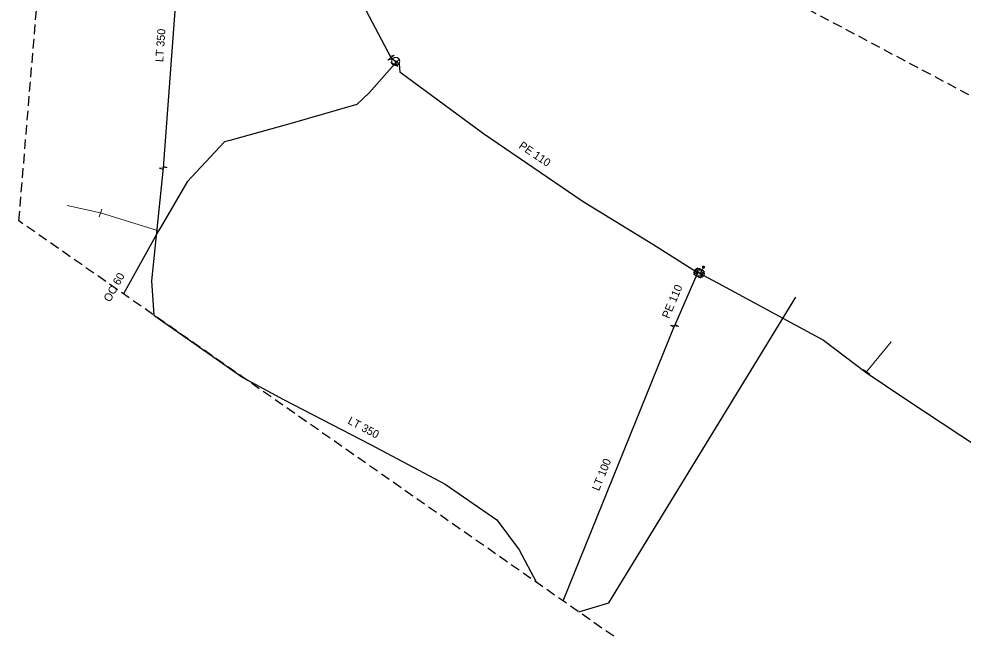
# Model space of a CAD drawing. Extents: x -692311 to -690519, y -971696 to -970899.
# Drawn here: x -692311.1 to -692193.2, y -971025.1 to -970948.8 of the extents above; entities that cross this region are included whole.
import ezdxf

# ---------------------------------------------------------------- set-up
doc = ezdxf.new("R2010")
doc.units = 0
doc.header["$LTSCALE"] = 0.4
doc.linetypes.add('MEDIUM_DASHED', pattern=[4.5, 3, -1.5])
for name, color, linetype, lineweight in [('1', 7, 'MEDIUM_DASHED', 25), ('13', 7, 'Continuous', 13), ('14', 7, 'Continuous', 13), ('17', 7, 'Continuous', 25), ('34', 7, 'Continuous', 13), ('47', 7, 'Continuous', 13), ('9', 7, 'Continuous', 13)]:
    doc.layers.add(name, color=color, linetype=linetype, lineweight=lineweight)

msp = doc.modelspace()

# ---------------------------------------------------------------- linework, layer by layer
at = {"layer": '1'}
msp.add_lwpolyline([(-691377.453, -971285.953), (-691463.283, -971177.096), (-691580.514, -971177.096), (-691632.849, -971177.096), (-691781.481, -971235.711), (-691971.982, -971202.217), (-692089.213, -971128.947), (-692311.114, -970974.035), (-692304.834, -970898.672), (-692166.669, -970971.942), (-691976.169, -971133.134), (-691904.993, -971149.882), (-691798.229, -971170.816), (-691674.718, -971116.387), (-691582.607, -971118.48), (-691415.135, -971114.294)], dxfattribs=at)
at = {"layer": '13'}
msp.add_line((-692205.219, -970992.88), (-692202.131, -970989.14), dxfattribs=at)
msp.add_lwpolyline([(-692293.654, -970975.29), (-692300.92, -970973.039), (-692305.065, -970972.14)], dxfattribs=at)
at = {"layer": '14'}
for p, q in [((-692264.039, -970954.129), (-692263.91, -970954.239)), ((-692225.989, -970980.612), (-692225.71, -970980.76)), ((-692205.28, -970992.96), (-692205.219, -970992.88))]:
    msp.add_line(p, q, dxfattribs=at)
for points in [[(-692226.256, -970980.478), (-692225.989, -970980.612), (-692225.851, -970980.364), (-692225.59, -970979.829)], [(-692226.57, -970980.329), (-692226.256, -970980.478), (-692226.41, -970980.75)]]:
    msp.add_lwpolyline(points, dxfattribs=at)
at = {"layer": '17'}
for p, q in [((-692290.69, -970935.236), (-692293.079, -970967.41)), ((-692226.41, -970980.75), (-692229.19, -970987.149)), ((-692243.126, -971021.498), (-692229.19, -970987.149))]:
    msp.add_line(p, q, dxfattribs=at)
for points in [[(-692264.611, -970953.671), (-692273.526, -970936.77), (-692274.836, -970914.581)], [(-692264.611, -970953.671), (-692264.039, -970954.129), (-692264.201, -970954.489)], [(-692264.201, -970954.489), (-692267.35, -970958.059), (-692268.91, -970959.52), (-692277.27, -970961.91), (-692284.76, -970964), (-692285.42, -970964.18), (-692290.07, -970969.149), (-692293.355, -970974.751), (-692293.654, -970975.29), (-692298.028, -970983.171)], [(-692263.91, -970954.239), (-692263.6, -970954.44), (-692263.539, -970955.42), (-692253.05, -970963.14), (-692240.6, -970971.62), (-692231.92, -970976.949), (-692226.57, -970980.329)], [(-692293.079, -970967.41), (-692294.55, -970981.53), (-692294.267, -970985.796), (-692283.119, -970993.579), (-692278.07, -970996.329), (-692267.17, -971001.96), (-692257.84, -971006.93), (-692251.399, -971011.379), (-692248.609, -971015.129), (-692246.436, -971019.188)], [(-692225.71, -970980.76), (-692223.739, -970981.829), (-692210.6, -970988.94), (-692205.28, -970992.96), (-692200.44, -970996.21), (-692188.77, -971003.92)], [(-692241.179, -971022.858), (-692237.418, -971021.743), (-692214.058, -970983.563)]]:
    msp.add_lwpolyline(points, dxfattribs=at)
at = {"layer": '34'}
for p, q in [((-692263.587, -970953.856), (-692264.233, -970954.62)), ((-692301.067, -970973.516), (-692300.771, -970972.561)), ((-692226.3, -970979.907), (-692226.84, -970980.749)), ((-692225.974, -970980.995), (-692226.844, -970980.503)), ((-692226.287, -970980.12), (-692225.414, -970980.608)), ((-692225.476, -970980.318), (-692225.944, -970981.201)), ((-692205.618, -970992.579), (-692204.82, -970993.181))]:
    msp.add_line(p, q, dxfattribs=at)
at = {"layer": '47'}
for p, q in [((-692265.007, -970953.99), (-692264.517, -970953.848)), ((-692263.761, -970954.746), (-692264.068, -970954.338)), ((-692292.571, -970967.364), (-692293.058, -970967.21)), ((-692229.69, -970987.051), (-692229.265, -970987.335))]:
    msp.add_line(p, q, dxfattribs=at)
for points in [[(-692265.007, -970953.99), (-692264.214, -970953.351), (-692264.704, -970953.493)], [(-692263.761, -970954.746), (-692264.64, -970954.231), (-692264.333, -970954.639)], [(-692292.571, -970967.364), (-692293.586, -970967.455), (-692293.099, -970967.609)], [(-692229.69, -970987.051), (-692228.689, -970987.246), (-692229.114, -970986.962)]]:
    msp.add_lwpolyline(points, dxfattribs=at)
for points in [[(-692263.648, -970954.441), (-692263.618, -970954.399), (-692263.592, -970954.353), (-692263.572, -970954.306), (-692263.555, -970954.256), (-692263.544, -970954.204), (-692263.539, -970954.152), (-692263.54, -970954.1), (-692263.546, -970954.048), (-692263.556, -970953.997), (-692263.573, -970953.947), (-692263.594, -970953.899), (-692263.621, -970953.854), (-692263.651, -970953.812), (-692263.687, -970953.773), (-692263.726, -970953.738), (-692263.768, -970953.708), (-692263.814, -970953.682), (-692263.862, -970953.661), (-692263.911, -970953.645), (-692263.963, -970953.634), (-692264.015, -970953.629), (-692264.068, -970953.629), (-692264.12, -970953.635), (-692264.17, -970953.646), (-692264.22, -970953.663), (-692264.268, -970953.684), (-692264.313, -970953.711), (-692264.355, -970953.741), (-692264.394, -970953.777), (-692264.429, -970953.816), (-692264.459, -970953.858), (-692264.485, -970953.904), (-692264.507, -970953.952), (-692264.522, -970954.001), (-692264.533, -970954.053), (-692264.538, -970954.104), (-692264.538, -970954.157), (-692264.533, -970954.209), (-692264.521, -970954.26), (-692264.504, -970954.31), (-692264.483, -970954.358), (-692264.457, -970954.403), (-692264.426, -970954.445), (-692264.39, -970954.484), (-692264.351, -970954.519), (-692264.309, -970954.549), (-692264.263, -970954.575), (-692264.216, -970954.596), (-692264.166, -970954.612), (-692264.114, -970954.623), (-692264.063, -970954.628), (-692264.011, -970954.628), (-692263.959, -970954.622), (-692263.907, -970954.611), (-692263.857, -970954.594), (-692263.809, -970954.573), (-692263.765, -970954.547), (-692263.722, -970954.516), (-692263.683, -970954.48)], [(-692263.975, -970954.18), (-692263.969, -970954.173), (-692263.965, -970954.165), (-692263.962, -970954.158), (-692263.959, -970954.15), (-692263.957, -970954.141), (-692263.957, -970954.132), (-692263.957, -970954.124), (-692263.957, -970954.115), (-692263.96, -970954.107), (-692263.962, -970954.099), (-692263.966, -970954.091), (-692263.97, -970954.083), (-692263.975, -970954.077), (-692263.98, -970954.07), (-692263.987, -970954.065), (-692263.994, -970954.059), (-692264.002, -970954.055), (-692264.009, -970954.052), (-692264.017, -970954.049), (-692264.026, -970954.047), (-692264.035, -970954.047), (-692264.043, -970954.047), (-692264.052, -970954.047), (-692264.061, -970954.049), (-692264.068, -970954.052), (-692264.076, -970954.056), (-692264.084, -970954.06), (-692264.09, -970954.065), (-692264.097, -970954.07), (-692264.102, -970954.077), (-692264.108, -970954.084), (-692264.112, -970954.092), (-692264.115, -970954.099), (-692264.118, -970954.107), (-692264.12, -970954.116), (-692264.121, -970954.124), (-692264.12, -970954.133), (-692264.12, -970954.142), (-692264.118, -970954.151), (-692264.115, -970954.158), (-692264.111, -970954.166), (-692264.107, -970954.174), (-692264.102, -970954.18), (-692264.097, -970954.187), (-692264.09, -970954.192), (-692264.083, -970954.198), (-692264.075, -970954.202), (-692264.068, -970954.205), (-692264.06, -970954.208), (-692264.051, -970954.21), (-692264.043, -970954.211), (-692264.034, -970954.21), (-692264.025, -970954.21), (-692264.017, -970954.207), (-692264.009, -970954.205), (-692264.001, -970954.201), (-692263.993, -970954.197), (-692263.987, -970954.192), (-692263.98, -970954.187)], [(-692225.803, -970980.691), (-692225.784, -970980.642), (-692225.769, -970980.592), (-692225.76, -970980.541), (-692225.756, -970980.489), (-692225.757, -970980.436), (-692225.765, -970980.384), (-692225.778, -970980.334), (-692225.795, -970980.284), (-692225.817, -970980.237), (-692225.845, -970980.192), (-692225.877, -970980.151), (-692225.914, -970980.113), (-692225.953, -970980.08), (-692225.997, -970980.05), (-692226.042, -970980.025), (-692226.091, -970980.006), (-692226.141, -970979.991), (-692226.193, -970979.982), (-692226.244, -970979.978), (-692226.297, -970979.979), (-692226.349, -970979.987), (-692226.4, -970979.999), (-692226.45, -970980.017), (-692226.497, -970980.039), (-692226.541, -970980.067), (-692226.582, -970980.099), (-692226.62, -970980.135), (-692226.653, -970980.175), (-692226.683, -970980.219), (-692226.708, -970980.264), (-692226.727, -970980.313), (-692226.742, -970980.363), (-692226.752, -970980.415), (-692226.755, -970980.466), (-692226.754, -970980.519), (-692226.747, -970980.571), (-692226.735, -970980.622), (-692226.717, -970980.671), (-692226.694, -970980.719), (-692226.666, -970980.763), (-692226.634, -970980.804), (-692226.599, -970980.842), (-692226.558, -970980.875), (-692226.514, -970980.905), (-692226.469, -970980.93), (-692226.42, -970980.949), (-692226.37, -970980.964), (-692226.319, -970980.974), (-692226.267, -970980.977), (-692226.214, -970980.976), (-692226.162, -970980.969), (-692226.112, -970980.956), (-692226.063, -970980.939), (-692226.015, -970980.916), (-692225.97, -970980.888), (-692225.929, -970980.856), (-692225.892, -970980.82), (-692225.858, -970980.78), (-692225.828, -970980.736)], [(-692225.542, -970980.836), (-692225.521, -970980.788), (-692225.505, -970980.738), (-692225.495, -970980.687), (-692225.489, -970980.635), (-692225.489, -970980.582), (-692225.496, -970980.53), (-692225.507, -970980.479), (-692225.524, -970980.43), (-692225.545, -970980.382), (-692225.571, -970980.337), (-692225.602, -970980.294), (-692225.638, -970980.256), (-692225.676, -970980.221), (-692225.719, -970980.191), (-692225.764, -970980.165), (-692225.812, -970980.144), (-692225.862, -970980.128), (-692225.914, -970980.117), (-692225.965, -970980.112), (-692226.018, -970980.112), (-692226.07, -970980.119), (-692226.121, -970980.13), (-692226.171, -970980.146), (-692226.219, -970980.167), (-692226.263, -970980.194), (-692226.306, -970980.225), (-692226.345, -970980.26), (-692226.379, -970980.299), (-692226.409, -970980.342), (-692226.435, -970980.387), (-692226.456, -970980.435), (-692226.472, -970980.485), (-692226.483, -970980.537), (-692226.488, -970980.588), (-692226.488, -970980.641), (-692226.482, -970980.693), (-692226.471, -970980.744), (-692226.455, -970980.794), (-692226.433, -970980.842), (-692226.406, -970980.886), (-692226.375, -970980.929), (-692226.341, -970980.967), (-692226.301, -970981.002), (-692226.258, -970981.032), (-692226.213, -970981.058), (-692226.165, -970981.079), (-692226.115, -970981.095), (-692226.064, -970981.106), (-692226.012, -970981.111), (-692225.959, -970981.111), (-692225.907, -970981.105), (-692225.857, -970981.094), (-692225.807, -970981.077), (-692225.759, -970981.055), (-692225.714, -970981.029), (-692225.671, -970980.998), (-692225.633, -970980.963), (-692225.598, -970980.924), (-692225.568, -970980.881)], [(-692226.181, -970980.512), (-692226.177, -970980.504), (-692226.176, -970980.496), (-692226.174, -970980.488), (-692226.174, -970980.48), (-692226.174, -970980.471), (-692226.175, -970980.462), (-692226.177, -970980.454), (-692226.18, -970980.446), (-692226.184, -970980.438), (-692226.188, -970980.431), (-692226.194, -970980.424), (-692226.2, -970980.418), (-692226.206, -970980.412), (-692226.212, -970980.407), (-692226.221, -970980.403), (-692226.229, -970980.399), (-692226.237, -970980.398), (-692226.245, -970980.396), (-692226.253, -970980.396), (-692226.262, -970980.396), (-692226.271, -970980.397), (-692226.279, -970980.399), (-692226.287, -970980.402), (-692226.296, -970980.406), (-692226.302, -970980.41), (-692226.309, -970980.416), (-692226.315, -970980.422), (-692226.321, -970980.428), (-692226.326, -970980.434), (-692226.33, -970980.443), (-692226.334, -970980.451), (-692226.335, -970980.459), (-692226.337, -970980.467), (-692226.337, -970980.475), (-692226.337, -970980.484), (-692226.337, -970980.492), (-692226.334, -970980.501), (-692226.331, -970980.509), (-692226.327, -970980.518), (-692226.323, -970980.524), (-692226.317, -970980.531), (-692226.311, -970980.537), (-692226.305, -970980.543), (-692226.299, -970980.548), (-692226.29, -970980.552), (-692226.282, -970980.556), (-692226.274, -970980.557), (-692226.266, -970980.559), (-692226.258, -970980.559), (-692226.249, -970980.559), (-692226.241, -970980.559), (-692226.232, -970980.556), (-692226.224, -970980.553), (-692226.216, -970980.549), (-692226.209, -970980.545), (-692226.202, -970980.539), (-692226.196, -970980.533), (-692226.19, -970980.527), (-692226.185, -970980.521)], [(-692225.915, -970980.648), (-692225.911, -970980.64), (-692225.909, -970980.632), (-692225.908, -970980.624), (-692225.907, -970980.616), (-692225.907, -970980.607), (-692225.908, -970980.598), (-692225.909, -970980.59), (-692225.912, -970980.582), (-692225.916, -970980.574), (-692225.92, -970980.566), (-692225.925, -970980.559), (-692225.931, -970980.553), (-692225.937, -970980.548), (-692225.944, -970980.542), (-692225.952, -970980.538), (-692225.96, -970980.534), (-692225.968, -970980.532), (-692225.976, -970980.531), (-692225.984, -970980.53), (-692225.993, -970980.53), (-692226.002, -970980.531), (-692226.01, -970980.532), (-692226.018, -970980.535), (-692226.027, -970980.539), (-692226.034, -970980.543), (-692226.041, -970980.548), (-692226.047, -970980.554), (-692226.052, -970980.56), (-692226.058, -970980.567), (-692226.062, -970980.575), (-692226.066, -970980.583), (-692226.068, -970980.591), (-692226.069, -970980.599), (-692226.07, -970980.607), (-692226.07, -970980.616), (-692226.07, -970980.624), (-692226.068, -970980.633), (-692226.065, -970980.641), (-692226.061, -970980.65), (-692226.057, -970980.657), (-692226.052, -970980.664), (-692226.046, -970980.67), (-692226.04, -970980.675), (-692226.033, -970980.681), (-692226.025, -970980.685), (-692226.017, -970980.689), (-692226.009, -970980.691), (-692226.001, -970980.692), (-692225.993, -970980.693), (-692225.984, -970980.693), (-692225.976, -970980.693), (-692225.967, -970980.691), (-692225.959, -970980.688), (-692225.951, -970980.684), (-692225.943, -970980.68), (-692225.936, -970980.675), (-692225.93, -970980.669), (-692225.925, -970980.663), (-692225.919, -970980.656)]]:
    msp.add_lwpolyline(points, close=True, dxfattribs=at)
at = {"layer": '9'}
for points in [[(-692225.716, -970979.829), (-692225.716, -970979.842), (-692225.713, -970979.855), (-692225.711, -970979.868), (-692225.706, -970979.88), (-692225.7, -970979.892), (-692225.693, -970979.903), (-692225.684, -970979.913), (-692225.674, -970979.923), (-692225.664, -970979.931), (-692225.654, -970979.938), (-692225.642, -970979.944), (-692225.63, -970979.949), (-692225.617, -970979.952), (-692225.603, -970979.954), (-692225.591, -970979.956), (-692225.578, -970979.955), (-692225.565, -970979.953), (-692225.552, -970979.95), (-692225.539, -970979.945), (-692225.527, -970979.939), (-692225.517, -970979.932), (-692225.507, -970979.924), (-692225.497, -970979.914), (-692225.489, -970979.904), (-692225.482, -970979.893), (-692225.476, -970979.881), (-692225.471, -970979.869), (-692225.468, -970979.856), (-692225.466, -970979.843), (-692225.463, -970979.83), (-692225.465, -970979.817), (-692225.467, -970979.804), (-692225.47, -970979.791), (-692225.475, -970979.779), (-692225.48, -970979.767), (-692225.488, -970979.756), (-692225.495, -970979.746), (-692225.505, -970979.736), (-692225.516, -970979.728), (-692225.527, -970979.721), (-692225.539, -970979.715), (-692225.551, -970979.71), (-692225.564, -970979.707), (-692225.576, -970979.705), (-692225.59, -970979.704), (-692225.603, -970979.704), (-692225.615, -970979.706), (-692225.629, -970979.709), (-692225.641, -970979.714), (-692225.652, -970979.72), (-692225.664, -970979.727), (-692225.674, -970979.735), (-692225.684, -970979.745), (-692225.691, -970979.755), (-692225.699, -970979.766), (-692225.705, -970979.778), (-692225.71, -970979.79), (-692225.713, -970979.803), (-692225.715, -970979.816)], [(-692225.696, -970979.829), (-692225.696, -970979.84), (-692225.695, -970979.851), (-692225.691, -970979.862), (-692225.688, -970979.872), (-692225.683, -970979.882), (-692225.677, -970979.891), (-692225.669, -970979.9), (-692225.662, -970979.908), (-692225.652, -970979.915), (-692225.644, -970979.921), (-692225.634, -970979.926), (-692225.624, -970979.93), (-692225.613, -970979.933), (-692225.602, -970979.936), (-692225.591, -970979.936), (-692225.58, -970979.936), (-692225.569, -970979.934), (-692225.558, -970979.931), (-692225.548, -970979.927), (-692225.538, -970979.922), (-692225.529, -970979.916), (-692225.52, -970979.909), (-692225.512, -970979.901), (-692225.505, -970979.892), (-692225.499, -970979.883), (-692225.494, -970979.873), (-692225.49, -970979.863), (-692225.487, -970979.852), (-692225.485, -970979.841), (-692225.483, -970979.83), (-692225.483, -970979.819), (-692225.485, -970979.808), (-692225.489, -970979.797), (-692225.493, -970979.787), (-692225.498, -970979.777), (-692225.504, -970979.768), (-692225.511, -970979.759), (-692225.519, -970979.751), (-692225.527, -970979.744), (-692225.537, -970979.738), (-692225.547, -970979.733), (-692225.556, -970979.729), (-692225.568, -970979.726), (-692225.578, -970979.724), (-692225.59, -970979.724), (-692225.601, -970979.723), (-692225.612, -970979.725), (-692225.623, -970979.728), (-692225.632, -970979.732), (-692225.642, -970979.737), (-692225.652, -970979.743), (-692225.661, -970979.75), (-692225.669, -970979.758), (-692225.676, -970979.767), (-692225.681, -970979.776), (-692225.686, -970979.786), (-692225.691, -970979.796), (-692225.694, -970979.807), (-692225.696, -970979.818)], [(-692225.677, -970979.829), (-692225.677, -970979.838), (-692225.676, -970979.847), (-692225.673, -970979.856), (-692225.669, -970979.864), (-692225.666, -970979.872), (-692225.661, -970979.88), (-692225.654, -970979.887), (-692225.649, -970979.893), (-692225.642, -970979.899), (-692225.634, -970979.904), (-692225.625, -970979.908), (-692225.618, -970979.911), (-692225.608, -970979.914), (-692225.6, -970979.915), (-692225.591, -970979.917), (-692225.581, -970979.916), (-692225.573, -970979.915), (-692225.564, -970979.912), (-692225.556, -970979.909), (-692225.548, -970979.905), (-692225.539, -970979.9), (-692225.532, -970979.894), (-692225.527, -970979.888), (-692225.521, -970979.881), (-692225.516, -970979.873), (-692225.512, -970979.865), (-692225.509, -970979.857), (-692225.505, -970979.848), (-692225.505, -970979.839), (-692225.502, -970979.83), (-692225.504, -970979.821), (-692225.505, -970979.812), (-692225.507, -970979.803), (-692225.511, -970979.795), (-692225.515, -970979.787), (-692225.52, -970979.779), (-692225.526, -970979.772), (-692225.532, -970979.766), (-692225.539, -970979.76), (-692225.547, -970979.755), (-692225.554, -970979.751), (-692225.563, -970979.748), (-692225.571, -970979.745), (-692225.581, -970979.744), (-692225.59, -970979.743), (-692225.598, -970979.743), (-692225.608, -970979.744), (-692225.617, -970979.747), (-692225.625, -970979.75), (-692225.632, -970979.754), (-692225.641, -970979.759), (-692225.647, -970979.765), (-692225.654, -970979.771), (-692225.659, -970979.778), (-692225.664, -970979.786), (-692225.669, -970979.794), (-692225.672, -970979.802), (-692225.674, -970979.811), (-692225.676, -970979.82)], [(-692225.657, -970979.829), (-692225.657, -970979.836), (-692225.656, -970979.843), (-692225.654, -970979.85), (-692225.652, -970979.856), (-692225.649, -970979.862), (-692225.645, -970979.868), (-692225.641, -970979.874), (-692225.636, -970979.879), (-692225.63, -970979.883), (-692225.624, -970979.887), (-692225.618, -970979.89), (-692225.612, -970979.893), (-692225.605, -970979.894), (-692225.598, -970979.897), (-692225.591, -970979.897), (-692225.583, -970979.897), (-692225.576, -970979.895), (-692225.57, -970979.894), (-692225.564, -970979.891), (-692225.556, -970979.888), (-692225.552, -970979.884), (-692225.546, -970979.88), (-692225.541, -970979.875), (-692225.537, -970979.869), (-692225.532, -970979.863), (-692225.529, -970979.857), (-692225.527, -970979.851), (-692225.525, -970979.844), (-692225.524, -970979.837), (-692225.522, -970979.83), (-692225.522, -970979.823), (-692225.524, -970979.816), (-692225.526, -970979.809), (-692225.529, -970979.803), (-692225.532, -970979.796), (-692225.536, -970979.791), (-692225.539, -970979.785), (-692225.544, -970979.78), (-692225.551, -970979.776), (-692225.556, -970979.772), (-692225.563, -970979.769), (-692225.569, -970979.766), (-692225.576, -970979.764), (-692225.583, -970979.763), (-692225.59, -970979.763), (-692225.597, -970979.763), (-692225.603, -970979.763), (-692225.61, -970979.765), (-692225.617, -970979.768), (-692225.623, -970979.771), (-692225.629, -970979.775), (-692225.635, -970979.779), (-692225.64, -970979.784), (-692225.644, -970979.79), (-692225.647, -970979.795), (-692225.651, -970979.802), (-692225.654, -970979.808), (-692225.654, -970979.815), (-692225.657, -970979.822)], [(-692225.637, -970979.829), (-692225.637, -970979.834), (-692225.637, -970979.839), (-692225.636, -970979.844), (-692225.634, -970979.848), (-692225.632, -970979.853), (-692225.629, -970979.857), (-692225.625, -970979.86), (-692225.622, -970979.864), (-692225.619, -970979.867), (-692225.615, -970979.87), (-692225.61, -970979.872), (-692225.605, -970979.874), (-692225.601, -970979.875), (-692225.596, -970979.877), (-692225.591, -970979.877), (-692225.586, -970979.877), (-692225.581, -970979.876), (-692225.576, -970979.875), (-692225.571, -970979.873), (-692225.566, -970979.871), (-692225.563, -970979.868), (-692225.559, -970979.865), (-692225.556, -970979.861), (-692225.553, -970979.858), (-692225.549, -970979.854), (-692225.548, -970979.849), (-692225.546, -970979.845), (-692225.544, -970979.84), (-692225.544, -970979.835), (-692225.543, -970979.83), (-692225.543, -970979.825), (-692225.544, -970979.82), (-692225.544, -970979.815), (-692225.547, -970979.811), (-692225.549, -970979.806), (-692225.552, -970979.802), (-692225.554, -970979.798), (-692225.558, -970979.795), (-692225.561, -970979.792), (-692225.566, -970979.789), (-692225.571, -970979.787), (-692225.575, -970979.785), (-692225.58, -970979.784), (-692225.585, -970979.783), (-692225.59, -970979.783), (-692225.595, -970979.783), (-692225.6, -970979.784), (-692225.605, -970979.784), (-692225.608, -970979.786), (-692225.614, -970979.788), (-692225.618, -970979.791), (-692225.62, -970979.794), (-692225.625, -970979.797), (-692225.627, -970979.801), (-692225.63, -970979.805), (-692225.632, -970979.81), (-692225.635, -970979.814), (-692225.636, -970979.819), (-692225.637, -970979.824)], [(-692225.617, -970979.829), (-692225.617, -970979.832), (-692225.618, -970979.835), (-692225.617, -970979.837), (-692225.615, -970979.84), (-692225.615, -970979.843), (-692225.613, -970979.845), (-692225.61, -970979.847), (-692225.608, -970979.849), (-692225.607, -970979.851), (-692225.605, -970979.853), (-692225.602, -970979.855), (-692225.598, -970979.856), (-692225.597, -970979.856), (-692225.593, -970979.857), (-692225.591, -970979.857), (-692225.588, -970979.857), (-692225.585, -970979.857), (-692225.581, -970979.856), (-692225.58, -970979.855), (-692225.576, -970979.854), (-692225.575, -970979.852), (-692225.571, -970979.85), (-692225.57, -970979.848), (-692225.569, -970979.846), (-692225.566, -970979.844), (-692225.566, -970979.841), (-692225.564, -970979.838), (-692225.564, -970979.836), (-692225.563, -970979.833), (-692225.561, -970979.83), (-692225.563, -970979.827), (-692225.563, -970979.824), (-692225.564, -970979.821), (-692225.565, -970979.819), (-692225.566, -970979.816), (-692225.568, -970979.814), (-692225.569, -970979.811), (-692225.571, -970979.809), (-692225.574, -970979.808), (-692225.576, -970979.806), (-692225.578, -970979.805), (-692225.581, -970979.804), (-692225.583, -970979.803), (-692225.587, -970979.803), (-692225.59, -970979.802), (-692225.593, -970979.803), (-692225.596, -970979.802), (-692225.598, -970979.804), (-692225.601, -970979.804), (-692225.603, -970979.805), (-692225.605, -970979.807), (-692225.608, -970979.808), (-692225.61, -970979.81), (-692225.612, -970979.813), (-692225.614, -970979.815), (-692225.615, -970979.818), (-692225.615, -970979.82), (-692225.617, -970979.823), (-692225.617, -970979.826)], [(-692225.598, -970979.829), (-692225.598, -970979.831), (-692225.598, -970979.831), (-692225.597, -970979.831), (-692225.597, -970979.833), (-692225.598, -970979.834), (-692225.596, -970979.834), (-692225.596, -970979.834), (-692225.596, -970979.836), (-692225.596, -970979.836), (-692225.595, -970979.837), (-692225.593, -970979.837), (-692225.593, -970979.837), (-692225.593, -970979.838), (-692225.591, -970979.838), (-692225.591, -970979.838), (-692225.59, -970979.838), (-692225.588, -970979.838), (-692225.588, -970979.837), (-692225.588, -970979.837), (-692225.586, -970979.837), (-692225.586, -970979.836), (-692225.586, -970979.836), (-692225.585, -970979.835), (-692225.585, -970979.835), (-692225.583, -970979.834), (-692225.583, -970979.833), (-692225.581, -970979.832), (-692225.581, -970979.832), (-692225.581, -970979.831), (-692225.581, -970979.83), (-692225.581, -970979.829), (-692225.581, -970979.828), (-692225.581, -970979.828), (-692225.583, -970979.827), (-692225.583, -970979.826), (-692225.583, -970979.825), (-692225.583, -970979.825), (-692225.585, -970979.824), (-692225.585, -970979.824), (-692225.586, -970979.823), (-692225.587, -970979.823), (-692225.588, -970979.822), (-692225.588, -970979.822), (-692225.588, -970979.822), (-692225.59, -970979.822), (-692225.591, -970979.822), (-692225.592, -970979.822), (-692225.592, -970979.822), (-692225.593, -970979.823), (-692225.593, -970979.822), (-692225.595, -970979.824), (-692225.595, -970979.824), (-692225.596, -970979.824), (-692225.596, -970979.824), (-692225.597, -970979.826), (-692225.597, -970979.827), (-692225.597, -970979.828), (-692225.598, -970979.828), (-692225.598, -970979.829)]]:
    msp.add_lwpolyline(points, close=True, dxfattribs=at)

# ---------------------------------------------------------------- texts
at = {"layer": '1'}
for s, rotation, p in [('LT 350', 86, (-692293.089, -970954.24)), ('PE 110', 326, (-692248.748, -970964.876)), ('OC 60 ', 61, (-692299.722, -970984.252)), ('PE 110', 67, (-692229.898, -970986.308)), ('LT 350', 332, (-692270.121, -970999.3)), ('LT 100', 68, (-692238.645, -971007.833))]:
    msp.add_text(s, height=1, rotation=rotation, dxfattribs=at).set_placement(p)

doc.saveas('drawing.dxf')
